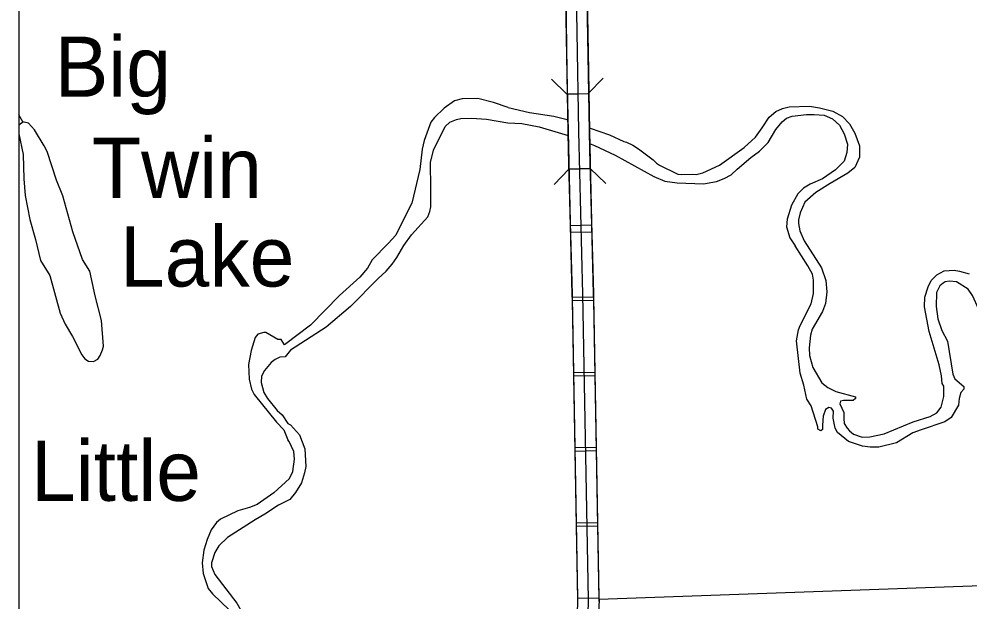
# Model space of a CAD drawing. Extents: x 1084508 to 1142749, y 1057638 to 1093403.
# Drawn here: x 1084508 to 1086600, y 1078446 to 1079728 of the extents above; entities that cross this region are included whole.
import ezdxf

# ---------------------------------------------------------------- set-up
doc = ezdxf.new("R2010")
doc.units = 0
for name, color, linetype in [('32', 7, 'Continuous'), ('35', 7, 'Continuous'), ('9', 7, 'Continuous'), ('DSN_DRFT_Named-Boundary', 7, 'Continuous'), ('Level 32', 7, 'Continuous'), ('Level 38', 7, 'Continuous'), ('Level 5', 7, 'Continuous'), ('Level 9', 7, 'Continuous')]:
    doc.layers.add(name, color=color, linetype=linetype)

msp = doc.modelspace()

# ---------------------------------------------------------------- linework, layer by layer
at = {"layer": '32'}
for p, q in [((1085762.8, 1079563.9), (1085715.8, 1079563.1)), ((1085766.3, 1079399.1), (1085719.3, 1079397.9)), ((1085769.8, 1079259), (1085722.8, 1079257.9)), ((1085726.3, 1079115.6), (1085773.3, 1079116.5)), ((1085729.3, 1078949.9), (1085776.4, 1078950.8)), ((1085732.3, 1078784.2), (1085779.4, 1078785.1)), ((1085735.3, 1078618.5), (1085782.4, 1078619.4)), ((1085738.3, 1078452.8), (1085785.4, 1078453.7))]:
    msp.add_line(p, q, dxfattribs=at)
for points in [[(1085582.3, 1087565.6), (1085613.6, 1086049.7), (1085631.6, 1085476.8), (1085635.2, 1085132), (1085645.3, 1084315.2), (1085646.8, 1084296.3), (1085657.9, 1083480.1), (1085664.5, 1083458.3), (1085672.9, 1082993.9), (1085690.4, 1081819.2), (1085728.9, 1080137.4), (1085740.3, 1079480.5)], [(1085712, 1079778.4), (1085714.9, 1079612.7)], [(1085759.1, 1079779.2), (1085762, 1079613.5)], [(1085714.9, 1079612.7), (1085717.2, 1079480), (1085718, 1079446.8)], [(1085762, 1079613.5), (1085764.3, 1079481), (1085765.1, 1079448)], [(1085740.3, 1079480.5), (1085749.3, 1079122.2), (1085761.5, 1078449.6), (1085760.6, 1078415.2), (1085763, 1078342.8)], [(1085718, 1079446.8), (1085722.2, 1079281.2)], [(1085765.1, 1079448), (1085769.2, 1079282.3)], [(1085722.2, 1079281.2), (1085726.2, 1079121.7), (1085726.3, 1079115.6)], [(1085769.2, 1079282.3), (1085773.2, 1079122.7), (1085773.3, 1079116.5)], [(1085726.3, 1079115.6), (1085729.3, 1078949.9)], [(1085773.3, 1079116.5), (1085776.4, 1078950.8)], [(1085729.3, 1078949.9), (1085732.3, 1078784.2)], [(1085776.4, 1078950.8), (1085779.4, 1078785.1)], [(1085732.3, 1078784.2), (1085735.3, 1078618.5)], [(1085779.4, 1078785.1), (1085782.4, 1078619.4)], [(1085735.3, 1078618.5), (1085738.3, 1078452.8)], [(1085782.4, 1078619.4), (1085785.4, 1078453.7)], [(1085738.3, 1078452.8), (1085738.4, 1078449.7), (1085737.5, 1078415.2), (1085738.6, 1078373.3)], [(1085785.4, 1078453.7), (1085785.5, 1078449.5), (1085784.6, 1078415.3), (1085786.1, 1078362.2)]]:
    msp.add_lwpolyline(points, dxfattribs=at)
at = {"layer": '35'}
for points in [[(1084647.6, 1079198.5), (1084626.6, 1079259.9), (1084604.3, 1079339.1), (1084590.5, 1079373.3), (1084569.8, 1079436.6), (1084563.7, 1079449.3), (1084542.3, 1079484.4), (1084528.6, 1079499.1), (1084519.3, 1079501.3), (1084516.2, 1079501.8), (1084507.9, 1079517.6)], [(1084516.8, 1079501.5), (1084511, 1079497.8), (1084507.9, 1079493.7)], [(1084507.9, 1079475.3), (1084517.1, 1079430), (1084518.9, 1079376.5), (1084521.2, 1079339.7), (1084531.5, 1079286.5), (1084544, 1079242.8), (1084555.4, 1079196.2)], [(1084555.4, 1079196.2), (1084576, 1079163.2), (1084598.8, 1079080.4), (1084609.9, 1079056.5), (1084625.6, 1079029.3), (1084646.1, 1078988.6), (1084653, 1078980), (1084660.7, 1078974.9), (1084672.1, 1078974), (1084681.4, 1078979.4), (1084686.8, 1078987.1), (1084692.1, 1078999.3), (1084693.7, 1079007.8), (1084689.7, 1079064.4), (1084675.7, 1079118.5), (1084663.8, 1079173), (1084647.6, 1079198.5)]]:
    msp.add_lwpolyline(points, dxfattribs=at)
at = {"layer": '9'}
for points in [[(1085585.6, 1079533.6), (1085552.7, 1079544.5), (1085518.7, 1079553.3), (1085483.8, 1079552.7), (1085467.4, 1079548.2), (1085444.7, 1079532.3), (1085423, 1079511.1), (1085415, 1079501.3), (1085400.4, 1079460.9), (1085395.6, 1079441.7), (1085390.7, 1079396.7), (1085373.3, 1079322.4), (1085353.9, 1079285.5), (1085337.7, 1079252.3), (1085320.9, 1079233.6), (1085286, 1079198.2), (1085275.2, 1079179.4), (1085258.8, 1079159.4)], [(1085585.6, 1079533.6), (1085632.4, 1079522.3), (1085686.2, 1079514.7), (1085712.3, 1079508), (1085716.4, 1079506.4)], [(1085299.2, 1079156.9), (1085316.7, 1079173.1), (1085330.2, 1079188.3), (1085340.3, 1079202.9), (1085355.4, 1079229.8), (1085372.3, 1079253), (1085408.3, 1079292.8), (1085413.1, 1079304), (1085414.9, 1079314.5), (1085415.3, 1079354.9), (1085414.3, 1079412.3), (1085421.2, 1079439.4), (1085446.5, 1079491.3), (1085457.2, 1079501), (1085471.3, 1079507.3), (1085481, 1079509), (1085504.3, 1079509.8), (1085537.4, 1079507.5), (1085584.6, 1079499.8)], [(1085584.6, 1079499.8), (1085615.6, 1079497.9), (1085653.6, 1079490.5), (1085695.7, 1079478.2), (1085717.2, 1079471.8)], [(1085258.8, 1079159.4), (1085214, 1079119.2), (1085150.3, 1079053.9), (1085092.7, 1079010.6)], [(1085299.2, 1079156.9), (1085238.1, 1079095.4), (1085184.7, 1079049.4), (1085106, 1078998.7), (1085094.2, 1078984.4)], [(1085092.7, 1079010.6), (1085085.2, 1079022.3), (1085077.9, 1079022.7), (1085051.3, 1079037.9), (1085046.9, 1079038.1), (1085034.1, 1079033.9), (1085028.4, 1079026.5), (1085019.2, 1078998.1), (1085013.6, 1078967.1), (1085014.9, 1078935.3), (1085020, 1078913.1), (1085025.8, 1078901), (1085075, 1078840.5), (1085091.2, 1078823.3), (1085100, 1078801.5)], [(1085094.2, 1078984.4), (1085082.3, 1078983.8), (1085071.8, 1078978.4), (1085063.2, 1078971.8), (1085048.3, 1078954), (1085042.4, 1078941.5), (1085041.3, 1078927.6), (1085047.4, 1078905.4), (1085055.3, 1078892.5), (1085076.7, 1078866), (1085087.3, 1078856.6), (1085099.7, 1078837.7)], [(1085099.7, 1078837.7), (1085105.8, 1078834.2), (1085125.4, 1078812.5), (1085137.2, 1078781.4), (1085139.5, 1078742.3), (1085137.1, 1078728.7), (1085129.8, 1078706.4), (1085116.6, 1078685.4), (1085104.3, 1078670.2)], [(1085103.6, 1078716.5), (1085110.9, 1078731.6), (1085114.7, 1078758.5), (1085112.9, 1078775.5), (1085102.7, 1078797.5), (1085100, 1078801.5)], [(1085103.6, 1078716.5), (1085068.9, 1078684.3), (1085032.6, 1078658.8), (1085015.5, 1078652), (1084989.6, 1078644.8), (1084951.5, 1078626.6), (1084942.9, 1078619.4), (1084931.4, 1078603.3), (1084922.3, 1078582.2), (1084915.2, 1078558), (1084911.7, 1078530.5), (1084913.4, 1078507.2), (1084924.8, 1078474.1), (1084934.4, 1078461.8), (1084971.4, 1078425.9), (1084984.6, 1078408), (1084996.7, 1078384.4), (1085046, 1078270.7), (1085087.9, 1078181.3), (1085104.2, 1078142.1), (1085120.9, 1078112.7), (1085125.9, 1078088)], [(1085104.3, 1078670.2), (1085079.2, 1078657.8), (1085049.6, 1078637.6), (1085028, 1078625.3), (1084967.5, 1078586.5), (1084948.3, 1078567.6), (1084939, 1078553.4), (1084931.9, 1078530.2), (1084931.8, 1078522.3), (1084939, 1078504.5), (1084987.6, 1078441.5), (1085025, 1078375.3), (1085047.9, 1078338.5), (1085086.6, 1078259.7), (1085113.5, 1078196.6), (1085124.7, 1078157.2)]]:
    msp.add_lwpolyline(points, dxfattribs=at)
at = {"layer": 'DSN_DRFT_Named-Boundary'}
msp.add_lwpolyline([(1084507.9, 1057640), (1142749.2, 1057640), (1142749.2, 1093403.4), (1084507.9, 1093403.4)], close=True, dxfattribs=at)
at = {"layer": 'Level 32'}
for p, q in [((1085714.7, 1079563), (1085761.8, 1079564.2)), ((1085718.8, 1079397.9), (1085765.9, 1079399)), ((1085721.9, 1079273.7), (1085769, 1079274.8)), ((1085726, 1079108.1), (1085773, 1079109)), ((1085729, 1078942.4), (1085776.1, 1078943.3)), ((1085732, 1078776.7), (1085779.1, 1078777.6)), ((1085735, 1078611), (1085782.1, 1078611.9))]:
    msp.add_line(p, q, dxfattribs=at)
for points in [[(1085582.5, 1087558.1), (1085613.6, 1086049.7), (1085631.6, 1085476.8), (1085635.2, 1085132), (1085645.3, 1084315.2), (1085646.8, 1084296.3), (1085657.9, 1083480.1), (1085664.5, 1083458.3), (1085672.9, 1082993.9), (1085690.4, 1081819.2), (1085728.9, 1080137.4), (1085740.3, 1079480.5)], [(1085711.7, 1079770.9), (1085714.6, 1079605.2)], [(1085758.8, 1079771.7), (1085761.7, 1079606)], [(1085714.6, 1079605.2), (1085716.8, 1079480), (1085717.8, 1079439.3)], [(1085761.7, 1079606), (1085763.8, 1079481), (1085764.8, 1079440.5)], [(1085740.3, 1079480.5), (1085749.3, 1079122.2), (1085761.5, 1078449.6), (1085760.6, 1078415.2), (1085763, 1078342.8)], [(1085717.8, 1079439.3), (1085721.9, 1079273.7)], [(1085764.8, 1079440.5), (1085769, 1079274.8)], [(1085721.9, 1079273.7), (1085725.7, 1079121.7), (1085726, 1079108.1)], [(1085769, 1079274.8), (1085772.8, 1079122.7), (1085773, 1079109)], [(1085726, 1079108.1), (1085729, 1078942.4)], [(1085773, 1079109), (1085776.1, 1078943.3)], [(1085729, 1078942.4), (1085732, 1078776.7)], [(1085776.1, 1078943.3), (1085779.1, 1078777.6)], [(1085732, 1078776.7), (1085735, 1078611)], [(1085779.1, 1078777.6), (1085782.1, 1078611.9)], [(1085735, 1078611), (1085738, 1078449.7), (1085737.9, 1078446.4)], [(1085782.1, 1078611.9), (1085785.1, 1078449.5), (1085785, 1078445.2)]]:
    msp.add_lwpolyline(points, dxfattribs=at)
at = {"layer": 'Level 38'}
for points in [[(1085714.8, 1079563.1), (1085680.7, 1079595.6)], [(1085794.4, 1079598.1), (1085761.8, 1079564.1)], [(1085686.7, 1079363.9), (1085719.3, 1079397.9)], [(1085766.3, 1079399), (1085800.4, 1079366.4)]]:
    msp.add_lwpolyline(points, dxfattribs=at)
at = {"layer": 'Level 5'}
msp.add_lwpolyline([(1085785.1, 1078450.5), (1086895.4, 1078489.8)], dxfattribs=at)
at = {"layer": 'Level 9'}
for points in [[(1085860, 1079450.7), (1085872.6, 1079442.5), (1085904.8, 1079418.1), (1085912.1, 1079410.5), (1085918.9, 1079406.7), (1085958.8, 1079386.5), (1085968, 1079385.6), (1085992.2, 1079386.7), (1085999.8, 1079385.5), (1086014.1, 1079389.6), (1086050.7, 1079406.5), (1086105, 1079445.2), (1086130.4, 1079467.9), (1086144.9, 1079488.7), (1086160.5, 1079512.5), (1086175, 1079524.8), (1086189.8, 1079531.5), (1086204.1, 1079534.7), (1086248.7, 1079536.7), (1086270.9, 1079532.7), (1086300.2, 1079525.2), (1086322.1, 1079513.6), (1086337, 1079497.5), (1086349, 1079476.9), (1086359, 1079449), (1086359.5, 1079424.1), (1086348.6, 1079401.2), (1086333.4, 1079389.1), (1086294.5, 1079365.9), (1086263, 1079346.1), (1086238.5, 1079325.1), (1086228.2, 1079301.3), (1086225.1, 1079286.3)], [(1086089.8, 1079397.5), (1086119.8, 1079423.5), (1086139, 1079437), (1086157.7, 1079456.2), (1086174.9, 1079484.7), (1086188.6, 1079501.8), (1086198.4, 1079509.8), (1086210.7, 1079514.1), (1086242.4, 1079517.8), (1086259, 1079518.3), (1086281.1, 1079516.4), (1086299.4, 1079508.7), (1086315.5, 1079494.3), (1086325.1, 1079475.2), (1086333.1, 1079452.5), (1086331.4, 1079434.2), (1086325.3, 1079415.6), (1086306.4, 1079396.1), (1086277.4, 1079376.5), (1086250.8, 1079364.5), (1086235.5, 1079355.6), (1086223.5, 1079343.4), (1086209.5, 1079318.1), (1086199.6, 1079287.4), (1086198.4, 1079270.9), (1086205.5, 1079246.6), (1086217.7, 1079228.6)], [(1085766.1, 1079488), (1085808.9, 1079473.6), (1085840.4, 1079458.7), (1085846.1, 1079457.3), (1085860, 1079450.7)], [(1085764.3, 1079454.4), (1085775.7, 1079450), (1085821.3, 1079428.1), (1085905.9, 1079381.5), (1085930.2, 1079371.3), (1085957.8, 1079367.5), (1086015.5, 1079365.1), (1086043.9, 1079370.2), (1086061.2, 1079377.3), (1086076.2, 1079385.2), (1086089.8, 1079397.5)], [(1086225.1, 1079286.3), (1086224.5, 1079278.1), (1086227.8, 1079261.8), (1086237.6, 1079239.6)], [(1086284.5, 1078867.9), (1086279.1, 1078853.8), (1086277.6, 1078833.5), (1086277.7, 1078824.1), (1086273.7, 1078821.4), (1086267.3, 1078824.9), (1086267.1, 1078830.3), (1086252.4, 1078876.1), (1086243, 1078891.1), (1086236.5, 1078921.8), (1086228.2, 1078947.9), (1086220.1, 1079019.2), (1086224.8, 1079044), (1086228.3, 1079052.9), (1086252.5, 1079101.1), (1086257.9, 1079124), (1086258, 1079153.1), (1086255.6, 1079166.2), (1086245.5, 1079184.4), (1086217.8, 1079228.4)], [(1086237.6, 1079239.6), (1086275.5, 1079180.5), (1086285.4, 1079152.5), (1086287.3, 1079127.7), (1086284.5, 1079101.8), (1086277.7, 1079083.8), (1086255.3, 1079044.8), (1086251.4, 1079032.1), (1086248.1, 1079004.2), (1086249.4, 1078987.2), (1086256.4, 1078960.7), (1086276.5, 1078927.1), (1086289.5, 1078916.6), (1086307.4, 1078908.2), (1086350.1, 1078895.9), (1086350.5, 1078892.2), (1086345, 1078887.9), (1086323.9, 1078888.3), (1086317.7, 1078886.2), (1086316.1, 1078880.7), (1086324.7, 1078861.9), (1086324.9, 1078848.6), (1086325.6, 1078837), (1086332.3, 1078826.8)], [(1086332.3, 1078826.8), (1086337.2, 1078821), (1086345.7, 1078814.1), (1086365.4, 1078807.6), (1086381.8, 1078807.7), (1086413.3, 1078814.6), (1086477.3, 1078840.7), (1086515.2, 1078852.9), (1086529.7, 1078861), (1086539.3, 1078873.4), (1086544.6, 1078896.6), (1086545, 1078919.6), (1086541.3, 1078925.5), (1086539.7, 1078942.1), (1086534.4, 1078966.5), (1086512.4, 1079039.7), (1086502.1, 1079094.5), (1086503.1, 1079116), (1086510.4, 1079138.6), (1086517.4, 1079152.1), (1086529.8, 1079164.9), (1086545.5, 1079173.4), (1086567.5, 1079175.2), (1086579.5, 1079173.2), (1086600.5, 1079166.7)], [(1086543.4, 1079146.8), (1086535.8, 1079140.9), (1086529.1, 1079125.8), (1086527.8, 1079095.2), (1086531.7, 1079068.2), (1086540.3, 1079042.1), (1086553.1, 1079018.6), (1086564.7, 1078945.9), (1086569.2, 1078935.4), (1086589, 1078919.1), (1086589, 1078913.1), (1086582.7, 1078905.3), (1086578.8, 1078892.3), (1086577.1, 1078877.4), (1086560.9, 1078850.3), (1086547.1, 1078840.9), (1086495.2, 1078823.5), (1086476.4, 1078816.7), (1086440.7, 1078795.1), (1086402.1, 1078785.4), (1086382.7, 1078785), (1086365.6, 1078787.2), (1086334.7, 1078797.9), (1086311, 1078817.5), (1086305.6, 1078827.4), (1086300.9, 1078848.9), (1086301.6, 1078864.7), (1086297.6, 1078871.2), (1086291.5, 1078872.9), (1086284.5, 1078867.9)], [(1086933, 1079049.2), (1086916.9, 1079018.6), (1086875.1, 1078977.9), (1086855.1, 1078958.2), (1086816, 1078928.3), (1086797, 1078916.8), (1086779.6, 1078902), (1086751.2, 1078887.6), (1086729.7, 1078884), (1086714.3, 1078884.3), (1086693.5, 1078891.7), (1086685.1, 1078899.9), (1086671.6, 1078929.6), (1086661.7, 1078967), (1086655.6, 1079011.3), (1086636.2, 1079057.8), (1086608, 1079119.1), (1086598.3, 1079133.2), (1086572.6, 1079149.6), (1086557.7, 1079150.9), (1086548, 1079149.5), (1086543.4, 1079146.8)]]:
    msp.add_lwpolyline(points, dxfattribs=at)

# ---------------------------------------------------------------- texts
at = {"layer": '35'}
for s, p in [('Big', (1084586.5, 1079557)), ('Twin', (1084668.6, 1079334.1)), ('Lake', (1084730.2, 1079139.1)), ('Little', (1084534.3, 1078666.9))]:
    msp.add_text(s, height=132.58, dxfattribs=at).set_placement(p)

doc.saveas('drawing.dxf')
